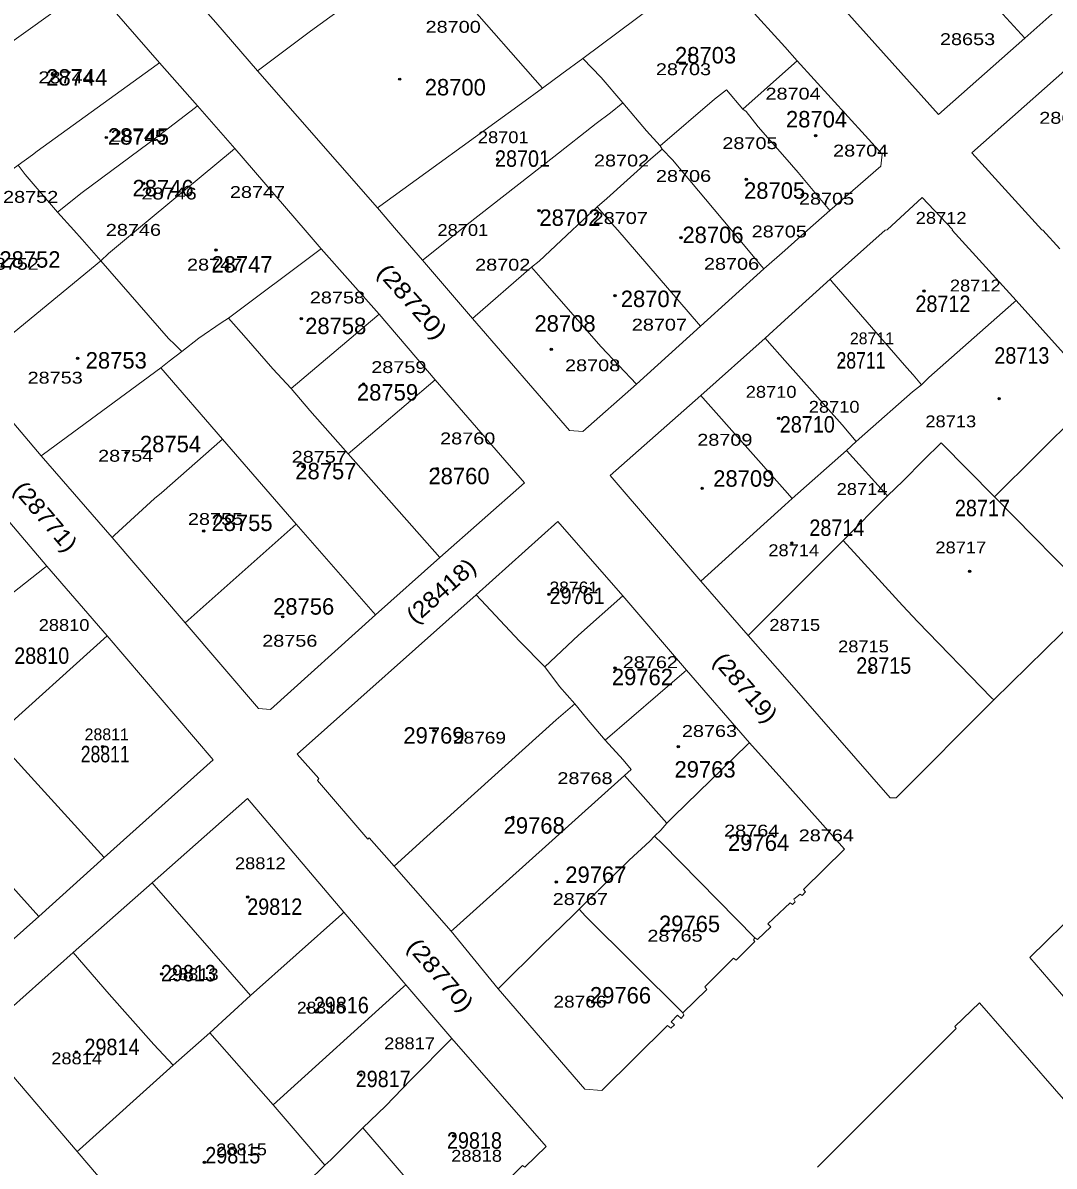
# Model space of a CAD drawing. Extents: x 650553 to 652508, y 239277 to 241647.
# Drawn here: x 651208.2 to 651434, y 240295.1 to 240545.4 of the extents above; entities that cross this region are included whole.
import ezdxf

# ---------------------------------------------------------------- set-up
doc = ezdxf.new("R2010")
doc.units = 0
doc.header["$PDMODE"] = 32
doc.header["$PDSIZE"] = 0.5
for name, color, linetype in [('19', 7, 'Continuous'), ('20', 7, 'Continuous'), ('6', 7, 'Continuous')]:
    doc.layers.add(name, color=color, linetype=linetype)
doc.layers.add('3', color=7, linetype='Continuous', lineweight=13)
doc.layers.add('5', color=7, linetype='Continuous', lineweight=13)

msp = doc.modelspace()

# ---------------------------------------------------------------- linework, layer by layer
at = {"layer": '3'}
for p, q in [((651427.585, 240542.041), (651441.626, 240554.652)), ((651375, 240540.13), (651377.735, 240537.102)), ((651384.876, 240504.346), (651380, 240500)), ((651306.59, 240480.68), (651295.65, 240493.45)), ((651285.4, 240415.78), (651299.48, 240428.33)), ((651211.64, 240349.75), (651225.94, 240362.65))]:
    msp.add_line(p, q, dxfattribs=at)
for points in [[(651375, 240540.13), (651358.51, 240558.37), (651340.48, 240578.22), (651331.44, 240588.29), (651322.55, 240598.18), (651307.18, 240615.11), (651291.88, 240631.98), (651276.83, 240648.43), (651261.75, 240665.07), (651247.26, 240681.25)], [(651295.65, 240493.45), (651290, 240500), (651285.79, 240504.89), (651259.52, 240534.92), (651250.39, 240545.47), (651235.33, 240562.59), (651220.57, 240579.93), (651206.08, 240596.78), (651191.08, 240613.86), (651178.77, 240628.25)], [(651273.44, 240495.96), (651269.97, 240500), (651254.58, 240517.89), (651246.43, 240527.23), (651238.05, 240536.69), (651223.17, 240553.84), (651208.09, 240571.29), (651193.7, 240587.9), (651178.92, 240605.09), (651167.95, 240618.06)], [(651386.452, 240550.075), (651408.664, 240525.362), (651427.585, 240542.041)], [(651435.22, 240495.92), (651431.49, 240500), (651431.297, 240500.117), (651415.962, 240516.979), (651443.339, 240541.167)], [(651377.735, 240537.102), (651396.328, 240516.675), (651396.051, 240514.017), (651384.876, 240504.346)], [(651384.9, 240489.28), (651396.96, 240500), (651397.423, 240500.111), (651405.055, 240507.195), (651411.75, 240500.156), (651411.62, 240500), (651425.66, 240484.62), (651443.85, 240464.41)], [(651370.39, 240491.55), (651375, 240495.54), (651380, 240500)], [(651298.47, 240467.24), (651286.14, 240481.62), (651273.44, 240495.96)], [(651342.54, 240466.28), (651356.51, 240478.98), (651370.39, 240491.55)], [(651370.68, 240476.36), (651375, 240480.28), (651384.9, 240489.28)], [(651226.59, 240411.22), (651213.41, 240426.47), (651200.34, 240441.8), (651180.96, 240463.99), (651164.75, 240482.79)], [(651306.59, 240480.68), (651327.82, 240456.19), (651330.77, 240455.91), (651342.54, 240466.28)], [(651356.63, 240423.18), (651336.78, 240446.28), (651356.58, 240463.81), (651370.68, 240476.36)], [(651243.67, 240414.03), (651227.69, 240432.76), (651212.18, 240450.64), (651196.19, 240469.45)], [(651299.48, 240428.33), (651318, 240444.73), (651298.47, 240467.24)], [(651443.85, 240464.41), (651465.39, 240441.08), (651443.12, 240419.06), (651420.78, 240397.15)], [(651339.51, 240419.96), (651325.29, 240436.21), (651307.4, 240420.15)], [(651420.78, 240397.15), (651399.39, 240375.71), (651398.09, 240375.7), (651375, 240402.11), (651367, 240411.26), (651356.63, 240423.18)], [(651307.4, 240420.15), (651268.24, 240385.28), (651272.95, 240379.94), (651272.67, 240379.55), (651283.66, 240366.65), (651284.02, 240366.96), (651289.44, 240360.76)], [(651375, 240379.16), (651367.27, 240387.8), (651353.46, 240403.68), (651339.51, 240419.96)], [(651243.67, 240414.03), (651259.78, 240395.31), (651262.41, 240395.05), (651285.4, 240415.78)], [(651225.94, 240362.65), (651249.82, 240384.05), (651226.59, 240411.22)], [(651375, 240351.66), (651376.14, 240352.75), (651376.67, 240352.34), (651377.25, 240352.97), (651376.99, 240353.54), (651378.35, 240354.65), (651378.78, 240354.37), (651379.57, 240355.11), (651379.06, 240355.63), (651388.11, 240364.51), (651375, 240379.16)], [(651236.46, 240357.1), (651257.33, 240375.59), (651278.47, 240350.7), (651292.04, 240334.8), (651302.06, 240323.02)], [(651450.72, 240362.35), (651428.65, 240340.77), (651441.12, 240326.31)], [(651289.44, 240360.76), (651301.93, 240346.53), (651312.23, 240333.92)], [(651220.02, 240298.27), (651198.5, 240323.44), (651219.19, 240341.88), (651236.46, 240357.1)], [(651174.64, 240351.27), (651191.4, 240331.77), (651211.64, 240349.75)], [(651368.41, 240345.08), (651369.05, 240344.71), (651371.94, 240347.48), (651371.31, 240348.14), (651375, 240351.66)], [(651352.66, 240328.65), (651357.95, 240333.78), (651357.52, 240334.36), (651363.79, 240340.61), (651364.33, 240340.16), (651368.45, 240344.23), (651368.14, 240344.6), (651368.41, 240345.08)], [(651312.23, 240333.92), (651331.18, 240311.94), (651334.95, 240311.64), (651349.33, 240325.86), (651350.06, 240325.28), (651350.87, 240326.02), (651350.15, 240326.66), (651351.48, 240328.17), (651352.34, 240327.39), (651352.91, 240328.13), (651352.66, 240328.65)], [(651426.69, 240250), (651461.4, 240280.6), (651417.67, 240330.87), (651412.21, 240325.69), (651412.52, 240325.19), (651382.18, 240294.85)], [(651302.06, 240323.02), (651322.74, 240299.4), (651318.09, 240294.84), (651317.54, 240295.2), (651302.54, 240280.28)], [(651285.91, 240263.75), (651271.96, 240250), (651271.2, 240249.25), (651271.62, 240248.84), (651266.6, 240243.84), (651261.32, 240250), (651246.32, 240267.52), (651220.02, 240298.27)]]:
    msp.add_lwpolyline(points, dxfattribs=at)
at = {"layer": '5'}
for p, q in [((651427.585, 240542.041), (651406.666, 240564.996)), ((651377.735, 240537.102), (651375.144, 240534.812)), ((651375.144, 240534.812), (651365.8, 240526.54)), ((651321.96, 240531.12), (651317.31, 240527.76)), ((651211.31, 240517.3), (651210.29, 240516.48)), ((651226.9, 240494.89), (651233.05, 240500)), ((651225.23, 240493.33), (651226.9, 240494.89)), ((651443.85, 240464.41), (651420.95, 240441.65)), ((651388.53, 240451.79), (651390.66, 240453.72)), ((651376.61, 240441.26), (651375, 240443.08)), ((651356.63, 240423.18), (651375, 240439.8)), ((651339.61, 240384.05), (651335.67, 240388.37)), ((651368.41, 240345.08), (651348.15, 240365.7)), ((651329.99, 240351.33), (651331.36, 240349.81)), ((651352.66, 240328.65), (651331.36, 240349.81)), ((651262.96, 240308.53), (651274.26, 240295.31))]:
    msp.add_line(p, q, dxfattribs=at)
for points in [[(651226.52, 240639.61), (651241.42, 240622.49), (651256.38, 240605.9), (651271.23, 240589.14), (651286.36, 240571.79), (651295.23, 240561.28), (651304.36, 240551.2), (651321.96, 240531.12)], [(651295.23, 240561.28), (651292.83, 240559.62), (651291.06, 240558.34), (651283.32, 240552.39), (651275.38, 240546.66), (651271.14, 240543.62)], [(651358.51, 240558.37), (651358.01, 240557.996), (651330.75, 240537.61)], [(651192.28, 240531.72), (651222.67, 240553.482), (651223.17, 240553.84)], [(651271.14, 240543.62), (651260.02, 240535.294), (651259.52, 240534.92)], [(651330.75, 240537.61), (651334.8, 240533.47), (651339.54, 240527.92), (651336.84, 240525.72), (651333.66, 240523.35), (651324.44, 240516.1), (651305.47, 240501.24), (651304.86, 240500.74), (651303.92, 240500)], [(651321.96, 240531.12), (651326.17, 240534.27), (651330.75, 240537.61)], [(651238.05, 240536.69), (651237.55, 240536.327), (651211.31, 240517.3)], [(651339.54, 240527.92), (651344.74, 240521.78), (651347.69, 240518.45), (651359.62, 240528.69), (651362.24, 240530.76), (651365.8, 240526.54), (651366.54, 240525.97), (651369.2, 240522.63), (651375, 240516.02)], [(651246.43, 240527.23), (651245.93, 240526.85), (651236.59, 240519.75)], [(651317.31, 240527.76), (651286.29, 240505.253), (651285.79, 240504.89)], [(651215.77, 240503.94), (651221.16, 240508.26), (651235.78, 240519.16), (651236.59, 240519.75)], [(651254.58, 240517.89), (651254.08, 240517.475), (651233.05, 240500)], [(651347.69, 240518.45), (651348.12, 240517.77), (651345.69, 240515.63), (651336, 240506.96), (651333.89, 240505.1), (651328.42, 240500)], [(651348.12, 240517.77), (651350.39, 240515.39), (651363.3, 240500)], [(651187.9, 240500), (651189.09, 240500.92), (651193.04, 240503.87), (651204.91, 240512.61), (651207.13, 240514.25), (651210.29, 240516.48)], [(651384.876, 240504.346), (651377.934, 240512.68), (651375, 240516.02)], [(651207.13, 240514.25), (651208.67, 240512.23), (651215.77, 240503.94), (651219.3, 240500)], [(651333.89, 240505.1), (651337.08, 240501.56), (651338.42, 240500)], [(651225.23, 240493.33), (651221.15, 240497.94), (651219.3, 240500)], [(651295.65, 240493.45), (651296.15, 240493.846), (651303.92, 240500)], [(651306.59, 240480.68), (651319.56, 240491.94), (651321.18, 240493.25), (651328.42, 240500)], [(651356.51, 240478.98), (651356.08, 240479.48), (651338.42, 240500)], [(651370.39, 240491.55), (651369.97, 240492.05), (651363.3, 240500)], [(651273.44, 240495.96), (651272.94, 240495.585), (651253.17, 240480.74), (651257.05, 240476.4), (651262.92, 240469.68), (651266.9, 240465.37)], [(651196.19, 240469.45), (651196.69, 240469.861), (651225.23, 240493.33), (651240.03, 240476.33)], [(651342.54, 240466.28), (651334.77, 240474.46), (651322.95, 240487.96), (651322.09, 240489.03), (651319.56, 240491.94)], [(651384.9, 240489.28), (651385.333, 240488.78), (651401.7, 240469.89), (651403.09, 240468.31), (651404.92, 240466.19), (651406.54, 240467.74)], [(651406.54, 240467.74), (651425.16, 240484.179), (651425.66, 240484.62)], [(651238.34, 240469.87), (651240.19, 240471.37), (651242.94, 240473.47), (651246.72, 240476.34), (651251.6, 240479.71), (651253.17, 240480.74)], [(651286.14, 240481.62), (651285.64, 240481.198), (651266.9, 240465.37), (651270.96, 240460.54), (651275.48, 240455.47), (651279.41, 240451.08)], [(651240.03, 240476.33), (651241.43, 240475.02), (651242.94, 240473.47)], [(651370.68, 240476.36), (651371.125, 240475.86), (651375, 240471.51)], [(651238.34, 240469.87), (651212.68, 240451.008), (651212.18, 240450.64)], [(651268.01, 240435.65), (651251.87, 240454.23), (651238.34, 240469.87)], [(651375, 240471.51), (651387.59, 240457.38), (651390.66, 240453.72), (651392.56, 240455.39), (651402.96, 240464.59), (651404.92, 240466.19)], [(651299.48, 240428.33), (651279.41, 240451.08), (651298.47, 240467.24)], [(651356.58, 240463.81), (651357.024, 240463.31), (651375, 240443.08)], [(651251.87, 240454.23), (651238.54, 240442.51), (651237.01, 240441.26)], [(651420.95, 240441.65), (651409.26, 240453.48), (651405.41, 240449.64)], [(651388.53, 240451.79), (651376.61, 240441.26), (651375, 240439.8)], [(651405.41, 240449.64), (651400.9, 240445.14), (651397.5, 240441.85), (651388.53, 240451.79)], [(651237.01, 240441.26), (651228.19, 240433.216), (651227.69, 240432.76)], [(651397.5, 240441.85), (651387.76, 240432.05), (651375, 240419.27)], [(651420.95, 240441.65), (651442.629, 240419.56), (651443.12, 240419.06)], [(651243.67, 240414.03), (651268.01, 240435.65), (651285.4, 240415.78)], [(651387.76, 240432.05), (651391.7, 240427.77), (651392.46, 240426.94), (651400.78, 240417.87), (651404.12, 240414.26)], [(651187.18, 240405.87), (651212.91, 240426.077), (651213.41, 240426.47)], [(651307.4, 240420.15), (651316.87, 240410.02), (651322.45, 240404.38), (651329.85, 240411.31), (651339.51, 240419.96)], [(651367, 240411.26), (651367.499, 240411.76), (651375, 240419.27)], [(651404.12, 240414.26), (651420.293, 240397.65), (651420.78, 240397.15)], [(651225.94, 240362.65), (651201.93, 240389.04), (651226.59, 240411.22)], [(651353.46, 240403.68), (651352.96, 240403.25), (651335.67, 240388.37), (651331.6, 240393.16), (651329.05, 240396.32), (651325.68, 240400.08), (651322.45, 240404.38)], [(651329.05, 240396.32), (651324.93, 240392.77), (651296.59, 240367.27), (651289.44, 240360.76)], [(651350.7, 240371.7), (651366.77, 240387.314), (651367.27, 240387.8)], [(651339.91, 240380.62), (651341.33, 240381.92), (651339.61, 240384.05)], [(651301.93, 240346.53), (651302.43, 240346.979), (651339.91, 240380.62)], [(651339.91, 240380.62), (651349.14, 240370.14), (651350.7, 240371.7)], [(651346.47, 240367.3), (651347.82, 240368.61), (651349.14, 240370.14)], [(651174.64, 240351.27), (651194.44, 240368.84), (651211.64, 240349.75)], [(651345.42, 240366.22), (651346.47, 240367.3), (651348.15, 240365.7)], [(651331.24, 240352.6), (651340.93, 240362.06), (651345.42, 240366.22)], [(651236.46, 240357.1), (651236.897, 240356.6), (651258, 240332.43)], [(651328.67, 240350.06), (651329.99, 240351.33), (651331.24, 240352.6)], [(651258, 240332.43), (651277.97, 240350.254), (651278.47, 240350.7)], [(651312.23, 240333.92), (651321.93, 240343.5), (651328.67, 240350.06)], [(651241.07, 240317.17), (651236.8, 240321.71), (651227.02, 240332.71), (651219.19, 240341.88)], [(651292.04, 240334.8), (651291.54, 240334.348), (651262.96, 240308.53), (651249.11, 240324.27)], [(651220.02, 240298.27), (651220.52, 240298.719), (651241.07, 240317.17), (651249.11, 240324.27), (651258, 240332.43)], [(651265.85, 240286.89), (651270.4, 240291.47), (651274.26, 240295.31), (651275.6, 240296.49), (651282.58, 240303.46), (651287.57, 240308.19), (651293.09, 240314.01), (651302.06, 240323.02)], [(651282.58, 240303.46), (651302.109, 240280.78), (651302.54, 240280.28)]]:
    msp.add_lwpolyline(points, dxfattribs=at)
at = {"layer": '6'}
for p in [(651354.187, 240538.41), (651214.965, 240534.045), (651290.681, 240533.085), (651226.401, 240520.315), (651381.757, 240520.724), (651312.083, 240515.53), (651234.645, 240510.28), (651366.573, 240511.155), (651321.204, 240504.3), (651352.241, 240498.375), (651250.459, 240495.68), (651337.837, 240485.69), (651405.455, 240486.692), (651269.123, 240480.665), (651220.134, 240471.985), (651323.862, 240473.925), (651387.657, 240471.5), (651282.74, 240466.35), (651421.941, 240463.135), (651373.669, 240458.81), (651230.826, 240451.315), (651269.477, 240448.26), (651298.833, 240447.785), (651356.902, 240443.495), (651247.745, 240434.13), (651376.545, 240431.525), (651415.466, 240425.315), (651323.389, 240420.295), (651265.04, 240415.35), (651337.828, 240404.165), (651393.844, 240403.875), (651298.204, 240390.455), (651225.599, 240386.935), (651351.678, 240386.91), (651315.437, 240371.425), (651367.058, 240366.255), (651324.959, 240357.27), (651257.409, 240354.01), (651349.386, 240347.975), (651238.567, 240337.135), (651270.617, 240329.615), (651332.068, 240331.485), (651219.857, 240320.075), (651282.157, 240315.055), (651302.454, 240301.65), (651247.906, 240295.895)]:
    msp.add_point(p, dxfattribs=at)

# ---------------------------------------------------------------- texts
at = {"layer": '19'}
for s, p in [('28703', (651350.958, 240536.527)), ('28744', (651213.268, 240531.677)), ('28700', (651296.154, 240529.522)), ('28704', (651375.255, 240522.517)), ('28745', (651226.768, 240518.745)), ('28746', (651232.168, 240507.43)), ('28705', (651366.077, 240506.891)), ('28702', (651321.26, 240500.964)), ('28706', (651352.579, 240497.192)), ('28752', (651203.01, 240491.804)), ('28747', (651249.447, 240490.727)), ('28707', (651339.08, 240483.183)), ('28758', (651269.965, 240477.255)), ('28708', (651320.18, 240477.795)), ('28753', (651221.908, 240469.712)), ('28759', (651281.304, 240462.707)), ('28754', (651233.787, 240451.392)), ('28757', (651267.805, 240445.465)), ('28760', (651296.963, 240444.387)), ('28709', (651359.328, 240443.849)), ('28755', (651249.447, 240434.149)), ('28756', (651262.946, 240415.829)), ('29762', (651337.136, 240400.384)), ('29769', (651291.479, 240387.594)), ('29763', (651350.845, 240380.162)), ('29768', (651313.431, 240367.874)), ('29764', (651362.568, 240364.103)), ('29767', (651326.932, 240357.098)), ('29765', (651347.449, 240346.321)), ('29766', (651332.331, 240330.695))]:
    msp.add_text(s, height=3.6, dxfattribs=at).set_placement(p)
for s, width, p in [('28701', 0.9, (651311.54, 240513.896)), ('28712', 0.9, (651403.605, 240482.105)), ('28711', 0.8, (651386.326, 240469.712)), ('28713', 0.9, (651420.884, 240470.79)), ('28710', 0.9, (651373.906, 240455.703)), ('28717', 0.9, (651412.244, 240437.383)), ('28714', 0.9, (651380.386, 240433.072)), ('29761', 0.9, (651323.482, 240418.161)), ('28810', 0.9, (651206.249, 240405.053)), ('28715', 0.9, (651390.646, 240402.898)), ('28811', 0.8, (651220.829, 240383.5)), ('29812', 0.9, (651257.275, 240350.092)), ('29813', 0.9, (651238.376, 240335.543)), ('29816', 0.9, (651271.854, 240328.539)), ('29814', 0.9, (651221.636, 240319.379)), ('29817', 0.9, (651281.034, 240312.374)), ('29818', 0.9, (651301.012, 240298.903)), ('29815', 0.9, (651248.096, 240295.67))]:
    msp.add_text(s, height=3.6, dxfattribs=dict(at, width=width)).set_placement(p)
for s, rotation, width, p in [('(28720)', 311.529, 1.2, (651285.484, 240490.67)), ('(28771)', 310.45, 1.1, (651205.82, 240443.108)), ('(28418)', 41.683, 1.1, (651294.092, 240413.656)), ('(28719)', 311.012, 1.1, (651359.047, 240405.58)), ('(28770)', 310.384, 1.15, (651292.052, 240343.015))]:
    msp.add_text(s, height=3.6, rotation=rotation, dxfattribs=dict(at, width=width)).set_placement(p)
at = {"layer": '20'}
for s, width, p in [('28700', 1.25, (651296.335, 240543.243)), ('28653', 1.25, (651408.978, 240540.538)), ('28744', 1.25, (651211.564, 240532.187)), ('28703', 1.25, (651346.77, 240533.959)), ('28704', 1.25, (651370.77, 240528.605)), ('28664', 1.25, (651430.724, 240523.31)), ('28745', 1.25, (651227.392, 240519.365)), ('28701', 1.15, (651307.786, 240519.067)), ('28705', 1.25, (651361.327, 240517.769)), ('28704', 1.25, (651385.575, 240516.141)), ('28702', 1.25, (651333.207, 240513.966)), ('28706', 1.25, (651346.781, 240510.589)), ('28747', 1.25, (651253.483, 240507.068)), ('28752', 1.25, (651203.815, 240506.004)), ('28746', 1.25, (651234.131, 240506.737)), ('28705', 1.25, (651378.096, 240505.606)), ('28707', 1.25, (651332.925, 240501.365)), ('28712', 1.15, (651403.678, 240501.404)), ('28746', 1.25, (651226.319, 240498.778)), ('28701', 1.15, (651298.941, 240498.754)), ('28705', 1.25, (651367.748, 240498.428)), ('28752', 1.25, (651199.562, 240491.343)), ('28747', 1.25, (651244.097, 240491.179)), ('28702', 1.25, (651307.187, 240491.158)), ('28706', 1.25, (651357.291, 240491.347)), ('28712', 1.15, (651411.154, 240486.593)), ('28758', 1.25, (651270.99, 240483.976)), ('28707', 1.25, (651341.499, 240478.037)), ('28759', 1.25, (651284.439, 240468.735)), ('28708', 1.25, (651326.878, 240469.121)), ('28753', 1.25, (651209.181, 240466.416)), ('28710', 1.15, (651366.449, 240463.315)), ('28710', 1.15, (651380.251, 240460.04)), ('28713', 1.15, (651405.784, 240456.85)), ('28760', 1.25, (651299.52, 240453.115)), ('28709', 1.25, (651355.83, 240452.82)), ('28754', 1.25, (651224.627, 240449.315)), ('28757', 1.25, (651267.014, 240449.087)), ('28714', 1.15, (651386.356, 240442.033)), ('28755', 1.25, (651244.29, 240435.476)), ('28714', 1.15, (651371.399, 240428.635)), ('28717', 1.15, (651407.981, 240429.242)), ('28761', 1.1, (651323.468, 240420.481)), ('28810', 1.15, (651211.616, 240412.257)), ('28715', 1.15, (651371.614, 240412.284)), ('28756', 1.25, (651260.559, 240408.812)), ('28715', 1.15, (651386.671, 240407.581)), ('28762', 1.25, (651339.512, 240404.121)), ('28769', 1.2, (651302.344, 240387.591)), ('28763', 1.25, (651352.462, 240389.057)), ('28768', 1.25, (651325.202, 240378.726)), ('28764', 1.25, (651361.709, 240367.246)), ('28764', 1.25, (651378.051, 240366.201)), ('28812', 1.15, (651254.596, 240360.095)), ('28767', 1.25, (651324.175, 240352.251)), ('28765', 1.25, (651344.912, 240344.225)), ('28813', 1.15, (651239.905, 240335.804)), ('28766', 1.2, (651324.343, 240329.79)), ('28816', 1.1, (651268.173, 240328.478)), ('28817', 1.15, (651287.281, 240320.667)), ('28814', 1.15, (651214.369, 240317.38)), ('28815', 1.15, (651250.472, 240297.451)), ('28818', 1.15, (651301.95, 240296.033))]:
    msp.add_text(s, height=2.6, dxfattribs=dict(at, width=width)).set_placement(p)
for s, p in [('28711', (651389.249, 240475.029)), ('28811', (651221.677, 240388.317))]:
    msp.add_text(s, height=2.6, dxfattribs=at).set_placement(p)

doc.saveas('drawing.dxf')
